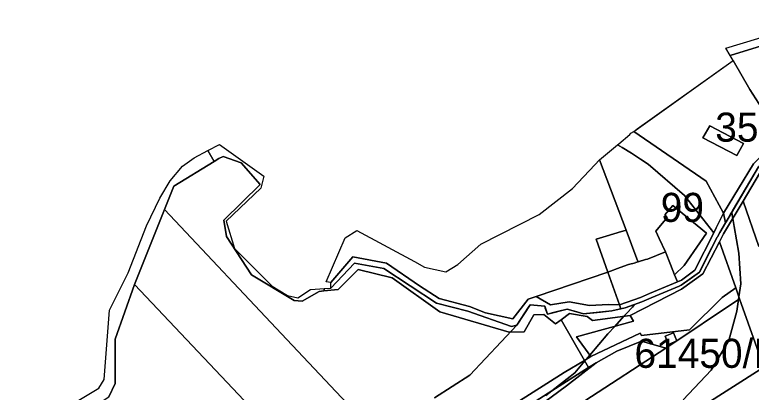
# Model space of a CAD drawing. Extents: x -522079 to -518792, y -1142400 to -1139961.
# Drawn here: x -521365.3 to -520985.3, y -1140287.7 to -1140093 of the extents above; entities that cross this region are included whole.
import ezdxf

# ---------------------------------------------------------------- set-up
doc = ezdxf.new("R2010")
doc.units = 0
for name, color, linetype in [('Bonity', 7, 'Continuous'), ('Hranice parcel', 7, 'Continuous'), ('Parcelní čísla', 7, 'Continuous'), ('Poz předměty', 7, 'Continuous'), ('Vnitřní kresba', 7, 'Continuous'), ('Značky bodu BP', 7, 'Continuous'), ('Značky kultur', 7, 'Continuous')]:
    doc.layers.add(name, color=color, linetype=linetype)

msp = doc.modelspace()

# ---------------------------------------------------------------- linework, layer by layer
at = {"layer": 'Bonity'}
for points in [[(-520999.73, -1140195.29), (-521008.55, -1140178.79), (-521045.99, -1140153.16), (-520994.7, -1140116.62), (-520985.99, -1140131.48), (-520970.51, -1140155.67), (-520977.56, -1140163.28), (-520984.14, -1140169.84)], [(-521006.77, -1140150.28), (-521010.35, -1140156.42), (-520992.72, -1140165.55), (-520989.25, -1140159.42)], [(-521146.28, -1140239.39), (-521156.43, -1140232.87), (-521173.55, -1140221.12), (-521190.8, -1140217.9), (-521202.15, -1140231.14), (-521204.62, -1140230.71), (-521194.92, -1140208.09), (-521188.9, -1140204.31), (-521159.02, -1140220.32), (-521153.92, -1140223.1), (-521142.98, -1140225.64), (-521136.78, -1140221.72), (-521124.89, -1140211.23), (-521094.81, -1140196.05), (-521077.51, -1140182.69), (-521066.01, -1140170.35), (-521063.7, -1140167.77), (-521049.86, -1140204.08), (-521050.38, -1140204.23), (-521052.23, -1140204.77), (-521060.17, -1140207.15), (-521065.43, -1140208.69), (-521059.29, -1140225.79), (-521096.26, -1140238.22), (-521100.42, -1140239.62), (-521108.36, -1140249.87), (-521122.43, -1140246.78), (-521130.62, -1140243.41)]]:
    msp.add_lwpolyline(points, close=True, dxfattribs=at)
at = {"layer": 'Hranice parcel'}
for points in [[(-520985.99, -1140131.48), (-520994.7, -1140116.62), (-520996.26, -1140113.95), (-520964.33, -1140104.24), (-520930.39, -1140100.03), (-520896.13, -1140105.14), (-520870.57, -1140104.77), (-520853.61, -1140106.69), (-520838.47, -1140119.76), (-520836.28, -1140125.74), (-520840.13, -1140128.04), (-520870.79, -1140146.36), (-520871.38, -1140143.8), (-520882.74, -1140135.78), (-520891.9, -1140126.87), (-520912.67, -1140122.89), (-520943.89, -1140122.58), (-520951.79, -1140130), (-520969.72, -1140157.28), (-520970.51, -1140155.67)], [(-520989.25, -1140159.42), (-520992.72, -1140165.55), (-521010.35, -1140156.42), (-521006.77, -1140150.28)], [(-521019.82, -1140186.27), (-521038.45, -1140170.03), (-521042.52, -1140167.42), (-521047.19, -1140164.44), (-521051.86, -1140161.45), (-521054.36, -1140160.13), (-521053.72, -1140159.58), (-521048.05, -1140154.68), (-521047.4, -1140154.12), (-521045.99, -1140153.16), (-521008.55, -1140178.79), (-520999.73, -1140195.29), (-521000.75, -1140197.43), (-521003.35, -1140202.91), (-521004.56, -1140205.45)], [(-521043.73, -1140220.34), (-521044.31, -1140218.8), (-521049.86, -1140204.08), (-521063.7, -1140167.77), (-521054.36, -1140160.13), (-521051.86, -1140161.45), (-521047.19, -1140164.44), (-521042.52, -1140167.42), (-521038.45, -1140170.03), (-521019.82, -1140186.27), (-521004.56, -1140205.45), (-521014.41, -1140224.73), (-521021.33, -1140229.82), (-521023.4, -1140230.68), (-521024.94, -1140227.06), (-521019.95, -1140222.33), (-521011.89, -1140210.69), (-521008.43, -1140205.69), (-521025.79, -1140191.41), (-521029.89, -1140196.26), (-521028.73, -1140197.48), (-521034.61, -1140204.63), (-521032.9, -1140208.45), (-521029.59, -1140215.24), (-521038.87, -1140219.06), (-521039.84, -1140219.26)], [(-521034.61, -1140204.63), (-521028.73, -1140197.48), (-521029.89, -1140196.26), (-521025.79, -1140191.41), (-521008.43, -1140205.69), (-521011.89, -1140210.69), (-521019.95, -1140222.33), (-521024.94, -1140227.06), (-521026.94, -1140221.87), (-521029.59, -1140215.24), (-521032.9, -1140208.45)], [(-521059.29, -1140225.79), (-521065.43, -1140208.69), (-521060.17, -1140207.15), (-521052.23, -1140204.77), (-521050.38, -1140204.23), (-521049.86, -1140204.08), (-521044.31, -1140218.8), (-521043.73, -1140220.34), (-521045.13, -1140220.72), (-521045.07, -1140220.96), (-521048.62, -1140221.83), (-521053.03, -1140223.33)], [(-521045.13, -1140220.72), (-521043.73, -1140220.34), (-521039.84, -1140219.26), (-521038.87, -1140219.06), (-521029.59, -1140215.24), (-521026.94, -1140221.87), (-521024.94, -1140227.06), (-521023.4, -1140230.68), (-521037.86, -1140236.76), (-521042.48, -1140238.76), (-521053.25, -1140242.58), (-521059.29, -1140225.79), (-521053.03, -1140223.33), (-521048.62, -1140221.83), (-521045.07, -1140220.96)], [(-521029.36, -1140265.01), (-521042, -1140261.25), (-521054.61, -1140266.48), (-521065.28, -1140272.43), (-521069.26, -1140274.95), (-521071.39, -1140271.24), (-521068.15, -1140269.31), (-521042.61, -1140257.18), (-521041.88, -1140258.46), (-521017.12, -1140255.44), (-521000.33, -1140238.84), (-520993.36, -1140233.77), (-520991.34, -1140239.5)], [(-521071.39, -1140271.24), (-521083.46, -1140250.25), (-521079.08, -1140247.03), (-521070.02, -1140248.6), (-521067.28, -1140250.75), (-521047.85, -1140248.01), (-521046.13, -1140251.03), (-521075.53, -1140259.14), (-521068.15, -1140269.31)], [(-521025.45, -1140257.06), (-521029.71, -1140258.76), (-521027.96, -1140262.97), (-521023.8, -1140261.15)], [(-521025.45, -1140257.06), (-521023.8, -1140261.15), (-521027.96, -1140262.97), (-521029.71, -1140258.76)], [(-521115.76, -1140299), (-521081.77, -1140277.41), (-521071.39, -1140271.24), (-521069.26, -1140274.95), (-521113.39, -1140302.86), (-521127.62, -1140312.94), (-521130.86, -1140309.33)]]:
    msp.add_lwpolyline(points, close=True, dxfattribs=at)
msp.add_lwpolyline([(-520978.89, -1140274.79), (-520991.34, -1140239.5), (-520993.36, -1140233.77), (-521001.72, -1140210.08), (-520999.64, -1140206.05), (-520989.57, -1140189.1), (-520981.4, -1140212.45)], dxfattribs=at)
at = {"layer": 'Parcelní čísla'}
for points in [[(-520875.21, -1140149), (-520981.4, -1140212.45), (-520989.57, -1140189.1), (-520978.85, -1140171.05), (-520967.99, -1140160), (-520949.73, -1140132.35), (-520942.17, -1140125.91), (-520910.05, -1140126.02), (-520892.49, -1140129.42), (-520884.78, -1140137.14), (-520873.63, -1140145.32), (-520873.12, -1140147.75)], [(-521144.75, -1140380.49), (-521166.55, -1140356.84), (-521138.04, -1140336), (-521105.44, -1140313.39), (-521071.25, -1140292.13), (-521029.36, -1140265.01), (-520991.34, -1140239.5), (-520978.89, -1140274.79)], [(-521042, -1140261.25), (-521029.36, -1140265.01), (-521071.25, -1140292.13), (-521105.44, -1140313.39), (-521138.04, -1140336), (-521166.55, -1140356.84), (-521170.88, -1140360.01), (-521186.8, -1140371.65), (-521202.24, -1140382.94), (-521262.52, -1140430.5), (-521393.25, -1140533.65), (-521431, -1140563.44), (-521501.14, -1140618.78), (-521510.5, -1140608.85), (-521177.32, -1140348.18), (-521127.62, -1140312.94), (-521125.23, -1140315.3), (-521106.97, -1140303.78), (-521080.73, -1140284.42), (-521065.28, -1140272.43), (-521054.61, -1140266.48)], [(-521113.39, -1140302.86), (-521069.26, -1140274.95), (-521065.28, -1140272.43), (-521080.73, -1140284.42), (-521106.97, -1140303.78), (-521125.23, -1140315.3), (-521127.62, -1140312.94)], [(-520943.46, -1140405.56), (-520937.19, -1140417.44), (-520924.28, -1140409.64), (-520923.06, -1140411.9), (-520913.58, -1140428.33), (-520906.37, -1140439.12), (-521031.07, -1140496.4), (-521039.03, -1140495.22), (-521144.75, -1140380.49), (-520978.89, -1140274.79), (-520959.74, -1140329.07), (-520948.85, -1140357.77), (-520931.92, -1140395.43), (-520930.52, -1140398.04)]]:
    msp.add_lwpolyline(points, close=True, dxfattribs=at)
at = {"layer": 'Poz předměty'}
msp.add_lwpolyline([(-521160.13, -1140329.24), (-521224.97, -1140260.52), (-521288.02, -1140193.37), (-521283.26, -1140181.41), (-521262.49, -1140168.67), (-521260.08, -1140167.19), (-521257.73, -1140166.05), (-521248.42, -1140169.45), (-521238.63, -1140180.63), (-521257.36, -1140198.93), (-521256.03, -1140207.29), (-521243.23, -1140227.2), (-521221.12, -1140240.34), (-521217.02, -1140240.66), (-521208.19, -1140235.66), (-521205.87, -1140235.43), (-521198.5, -1140234.71), (-521188.13, -1140224.34), (-521170.61, -1140228.65), (-521146.04, -1140246.18), (-521110.27, -1140256.62), (-521102.44, -1140256.49), (-521097.42, -1140247.68), (-521092.43, -1140247.55), (-521086.36, -1140252.38), (-521083.46, -1140250.25), (-521071.39, -1140271.24), (-521081.77, -1140277.41), (-521115.76, -1140299)], dxfattribs=at)
for points in [[(-521303.57, -1140232.09), (-521288.02, -1140193.37), (-521224.97, -1140260.52), (-521160.13, -1140329.24), (-521181.05, -1140344.19), (-521190.73, -1140351.49), (-521249.83, -1140288.83)], [(-521319.77, -1140291.98), (-521316.7, -1140289.98), (-521313.45, -1140283.14), (-521313.53, -1140260.28), (-521303.57, -1140232.09), (-521249.83, -1140288.83), (-521190.73, -1140351.49), (-521212.85, -1140368.17), (-521233.39, -1140383.74), (-521281.93, -1140333.33)]]:
    msp.add_lwpolyline(points, close=True, dxfattribs=at)
at = {"layer": 'Vnitřní kresba'}
for points in [[(-520840.13, -1140106.03), (-520833.95, -1140124.09), (-520832.38, -1140130.38), (-520834.57, -1140131.44), (-520836.28, -1140125.74), (-520838.47, -1140119.76), (-520853.61, -1140106.69), (-520870.57, -1140104.77), (-520896.13, -1140105.14), (-520930.39, -1140100.03), (-520964.33, -1140104.24), (-520996.26, -1140113.95), (-520998.41, -1140110.24), (-520941.45, -1140093.01), (-520920.41, -1140096.1), (-520898.59, -1140102.13), (-520887.39, -1140102.82), (-520865.88, -1140095.27), (-520850.56, -1140096.88)], [(-521212.75, -1140234.73), (-521205.52, -1140234.19), (-521205.87, -1140235.43), (-521208.19, -1140235.66), (-521217.02, -1140240.66), (-521221.12, -1140240.34), (-521243.23, -1140227.2), (-521256.03, -1140207.29), (-521257.36, -1140198.93), (-521238.63, -1140180.63), (-521248.42, -1140169.45), (-521257.73, -1140166.05), (-521260.08, -1140167.19), (-521262.49, -1140168.67), (-521265.75, -1140163.05), (-521259.67, -1140159.99), (-521236.81, -1140176.19), (-521238.42, -1140182.36), (-521256.3, -1140199.5), (-521251.89, -1140213.49), (-521232.49, -1140232.94), (-521224.62, -1140237.78), (-521219.26, -1140238.96)]]:
    msp.add_lwpolyline(points, close=True, dxfattribs=at)
for points in [[(-521333.16, -1140292.26), (-521321.89, -1140285.5), (-521319.14, -1140281.01), (-521316.46, -1140245.31), (-521306.79, -1140226.13), (-521297.37, -1140201.85), (-521290.54, -1140187.61), (-521285.21, -1140178.6), (-521278.81, -1140171.17), (-521272.67, -1140166.78), (-521265.75, -1140163.05), (-521262.49, -1140168.67), (-521283.26, -1140181.41), (-521288.02, -1140193.37), (-521303.57, -1140232.09), (-521313.53, -1140260.28), (-521313.45, -1140283.14), (-521316.7, -1140289.98)], [(-520981.64, -1140171.39), (-520997.26, -1140198.03), (-520998.6, -1140200.31), (-521001.55, -1140205.34), (-521002.8, -1140207.48), (-521002.93, -1140207.73), (-521012.11, -1140225.69), (-521021.42, -1140232.48), (-521022.45, -1140232.92), (-521036.95, -1140239.06), (-521041.79, -1140241.11), (-521050.32, -1140244.21), (-521057.24, -1140245.77), (-521071.82, -1140247.15), (-521080.35, -1140244.81), (-521090.52, -1140247.47), (-521091.88, -1140243.35), (-521099.45, -1140242.66), (-521106.23, -1140253.05), (-521109, -1140253.76), (-521131.5, -1140245.93), (-521147.64, -1140241.68), (-521174.85, -1140223.86), (-521189.97, -1140221.12), (-521202.32, -1140233.95), (-521202.15, -1140231.14), (-521190.8, -1140217.9), (-521173.55, -1140221.12), (-521156.43, -1140232.87), (-521146.28, -1140239.39), (-521130.62, -1140243.41), (-521122.43, -1140246.78), (-521108.36, -1140249.87), (-521100.42, -1140239.62), (-521096.26, -1140238.22), (-521088.86, -1140242.57), (-521079.19, -1140241.03), (-521068.77, -1140242.91), (-521058.99, -1140242.45), (-521053.25, -1140242.58), (-521042.48, -1140238.76), (-521037.86, -1140236.76), (-521023.4, -1140230.68), (-521021.33, -1140229.82), (-521014.41, -1140224.73), (-521004.56, -1140205.45), (-521003.35, -1140202.91), (-521000.75, -1140197.43), (-520999.73, -1140195.29), (-520984.14, -1140169.84)], [(-520978.85, -1140171.05), (-520989.57, -1140189.1), (-520999.64, -1140206.05), (-521001.72, -1140210.08), (-521010.26, -1140226.65), (-521021.33, -1140234.46), (-521047.85, -1140248.01), (-521067.28, -1140250.75), (-521070.02, -1140248.6), (-521079.08, -1140247.03), (-521083.46, -1140250.25), (-521086.36, -1140252.38), (-521092.43, -1140247.55), (-521097.42, -1140247.68), (-521102.44, -1140256.49), (-521110.27, -1140256.62), (-521146.04, -1140246.18), (-521170.61, -1140228.65), (-521188.13, -1140224.34), (-521198.5, -1140234.71), (-521205.87, -1140235.43), (-521205.52, -1140234.19), (-521202.32, -1140233.95), (-521189.97, -1140221.12), (-521174.85, -1140223.86), (-521147.64, -1140241.68), (-521131.5, -1140245.93), (-521109, -1140253.76), (-521106.23, -1140253.05), (-521099.45, -1140242.66), (-521091.88, -1140243.35), (-521090.52, -1140247.47), (-521080.35, -1140244.81), (-521071.82, -1140247.15), (-521057.24, -1140245.77), (-521050.32, -1140244.21), (-521041.79, -1140241.11), (-521036.95, -1140239.06), (-521022.45, -1140232.92), (-521021.42, -1140232.48), (-521012.11, -1140225.69), (-521002.93, -1140207.73), (-521002.8, -1140207.48), (-521001.55, -1140205.34), (-520998.6, -1140200.31), (-520997.26, -1140198.03), (-520981.64, -1140171.39)]]:
    msp.add_lwpolyline(points, dxfattribs=at)
at = {"layer": 'Značky bodu BP'}
for points in [[(-520970.51, -1140155.67), (-520985.99, -1140131.48), (-520994.7, -1140116.62), (-520996.26, -1140113.95), (-520998.41, -1140110.24), (-520941.45, -1140093.01)], [(-521333.16, -1140292.26), (-521321.89, -1140285.5), (-521319.14, -1140281.01), (-521316.46, -1140245.31), (-521306.79, -1140226.13), (-521297.37, -1140201.85), (-521290.54, -1140187.61), (-521285.21, -1140178.6), (-521278.81, -1140171.17), (-521272.67, -1140166.78), (-521265.75, -1140163.05), (-521259.67, -1140159.99), (-521236.81, -1140176.19), (-521238.42, -1140182.36), (-521256.3, -1140199.5), (-521251.89, -1140213.49), (-521232.49, -1140232.94), (-521224.62, -1140237.78), (-521219.26, -1140238.96), (-521212.75, -1140234.73), (-521205.52, -1140234.19), (-521202.32, -1140233.95), (-521202.15, -1140231.14), (-521204.62, -1140230.71), (-521194.92, -1140208.09), (-521188.9, -1140204.31), (-521159.02, -1140220.32), (-521153.92, -1140223.1), (-521142.98, -1140225.64), (-521136.78, -1140221.72), (-521124.89, -1140211.23), (-521094.81, -1140196.05), (-521077.51, -1140182.69), (-521066.01, -1140170.35), (-521063.7, -1140167.77), (-521049.86, -1140204.08), (-521050.38, -1140204.23), (-521052.23, -1140204.77), (-521060.17, -1140207.15), (-521065.43, -1140208.69), (-521059.29, -1140225.79), (-521055.82, -1140235.43), (-521053.25, -1140242.58), (-521052.54, -1140244.71), (-521057.24, -1140245.77), (-521063.1, -1140246.32), (-521071.82, -1140247.15), (-521075.39, -1140246.17), (-521080.35, -1140244.81), (-521082.35, -1140245.33), (-521083.25, -1140245.57), (-521087.96, -1140246.8), (-521090.52, -1140247.47), (-521091.26, -1140245.22), (-521091.58, -1140244.27), (-521091.88, -1140243.35), (-521099.45, -1140242.66), (-521100.22, -1140243.84), (-521106.23, -1140253.05), (-521130.6, -1140278.79), (-521148.82, -1140290.47)], [(-521020.52, -1140291.59), (-521006.02, -1140276.26), (-520996.96, -1140260.94), (-520992.81, -1140245.87), (-520991.93, -1140239.9), (-520991.71, -1140238.43), (-520990.74, -1140231.84), (-520991.78, -1140216), (-520994.11, -1140202.23), (-520994.85, -1140198), (-520995.34, -1140195.22), (-520995.41, -1140194.88), (-520995.24, -1140194.59), (-520994.97, -1140194.13), (-520981.64, -1140171.39)], [(-521091.26, -1140289.33), (-521088.2, -1140286.93), (-521076.41, -1140277.68), (-521071.21, -1140271.55), (-521070.83, -1140271.1), (-521070.48, -1140270.7), (-521068.68, -1140268.58), (-521059.39, -1140257.63), (-521055.79, -1140253.69), (-521051, -1140248.45), (-521048.39, -1140245.6), (-521048.14, -1140245.34), (-521047.94, -1140245.12), (-521046.67, -1140243.72), (-521045.54, -1140242.47), (-521041.79, -1140241.11), (-521036.95, -1140239.06), (-521022.45, -1140232.92), (-521021.86, -1140232.66), (-521021.42, -1140232.48), (-521018.03, -1140230.01), (-521012.11, -1140225.69), (-521007.83, -1140217.32), (-521003.4, -1140208.66), (-521002.92, -1140207.71), (-521002.8, -1140207.48), (-521001.55, -1140205.34), (-520998.6, -1140200.31), (-520998.32, -1140199.84), (-520997.26, -1140198.03), (-520996, -1140195.88), (-520995.41, -1140194.88), (-520995.34, -1140195.22), (-520994.85, -1140198), (-520994.11, -1140202.23), (-520991.78, -1140216), (-520990.74, -1140231.84), (-520991.71, -1140238.43), (-520991.93, -1140239.9), (-520992.81, -1140245.87), (-520996.96, -1140260.94), (-521006.02, -1140276.26), (-521020.52, -1140291.59)], [(-521148.82, -1140290.47), (-521130.6, -1140278.79), (-521106.23, -1140253.05), (-521100.22, -1140243.84), (-521099.45, -1140242.66), (-521091.88, -1140243.35), (-521091.58, -1140244.27), (-521091.26, -1140245.22), (-521090.52, -1140247.47), (-521087.96, -1140246.8), (-521083.25, -1140245.57), (-521082.35, -1140245.33), (-521080.35, -1140244.81), (-521075.39, -1140246.17), (-521071.82, -1140247.15), (-521063.1, -1140246.32), (-521057.24, -1140245.77), (-521052.54, -1140244.71), (-521050.32, -1140244.21), (-521045.54, -1140242.47), (-521046.67, -1140243.72), (-521047.94, -1140245.12), (-521048.14, -1140245.34), (-521048.39, -1140245.6), (-521051, -1140248.45), (-521055.79, -1140253.69), (-521059.39, -1140257.63), (-521068.68, -1140268.58), (-521070.48, -1140270.7), (-521070.83, -1140271.1), (-521071.21, -1140271.55), (-521076.41, -1140277.68), (-521088.2, -1140286.93), (-521091.26, -1140289.33)]]:
    msp.add_lwpolyline(points, dxfattribs=at)
for points in [[(-520969.27, -1140158.18), (-520976.2, -1140164.63), (-520981.64, -1140171.39), (-520994.97, -1140194.13), (-520995.24, -1140194.59), (-520995.41, -1140194.88), (-520996, -1140195.88), (-520997.26, -1140198.03), (-520998.32, -1140199.84), (-520998.6, -1140200.31), (-520999.73, -1140195.29), (-521008.55, -1140178.79), (-521045.99, -1140153.16), (-521044.19, -1140151.88), (-520994.7, -1140116.62), (-520985.99, -1140131.48), (-520970.51, -1140155.67), (-520969.72, -1140157.28)], [(-521045.99, -1140153.16), (-521008.55, -1140178.79), (-520999.73, -1140195.29), (-520998.6, -1140200.31), (-521001.55, -1140205.34), (-521002.8, -1140207.48), (-521002.92, -1140207.71), (-521003.4, -1140208.66), (-521007.83, -1140217.32), (-521012.11, -1140225.69), (-521018.03, -1140230.01), (-521021.42, -1140232.48), (-521021.86, -1140232.66), (-521022.45, -1140232.92), (-521036.95, -1140239.06), (-521041.79, -1140241.11), (-521045.54, -1140242.47), (-521050.32, -1140244.21), (-521052.54, -1140244.71), (-521053.25, -1140242.58), (-521055.82, -1140235.43), (-521059.29, -1140225.79), (-521065.43, -1140208.69), (-521060.17, -1140207.15), (-521052.23, -1140204.77), (-521050.38, -1140204.23), (-521049.86, -1140204.08), (-521063.7, -1140167.77), (-521054.36, -1140160.13), (-521053.72, -1140159.58), (-521048.05, -1140154.68), (-521047.4, -1140154.12)]]:
    msp.add_lwpolyline(points, close=True, dxfattribs=at)
at = {"layer": 'Značky kultur'}
for points in [[(-521042.61, -1140257.18), (-521068.15, -1140269.31), (-521075.53, -1140259.14), (-521046.13, -1140251.03), (-521047.85, -1140248.01), (-521021.33, -1140234.46), (-521010.26, -1140226.65), (-521001.72, -1140210.08), (-520993.36, -1140233.77), (-521000.33, -1140238.84), (-521017.12, -1140255.44), (-521041.88, -1140258.46)], [(-521053.25, -1140242.58), (-521058.99, -1140242.45), (-521068.77, -1140242.91), (-521079.19, -1140241.03), (-521088.86, -1140242.57), (-521096.26, -1140238.22), (-521059.29, -1140225.79)]]:
    msp.add_lwpolyline(points, close=True, dxfattribs=at)

# ---------------------------------------------------------------- texts
at = {"layer": 'Značky bodu BP'}
for s, p in [('35800/II.', (-521003.91, -1140158.47)), ('99', (-521032.02, -1140199.85))]:
    msp.add_text(s, height=15, rotation=360, dxfattribs=at).set_placement(p)
msp.add_text('61450/III.', height=15, dxfattribs=at).set_placement((-521045.59, -1140275.09))

doc.saveas('drawing.dxf')
